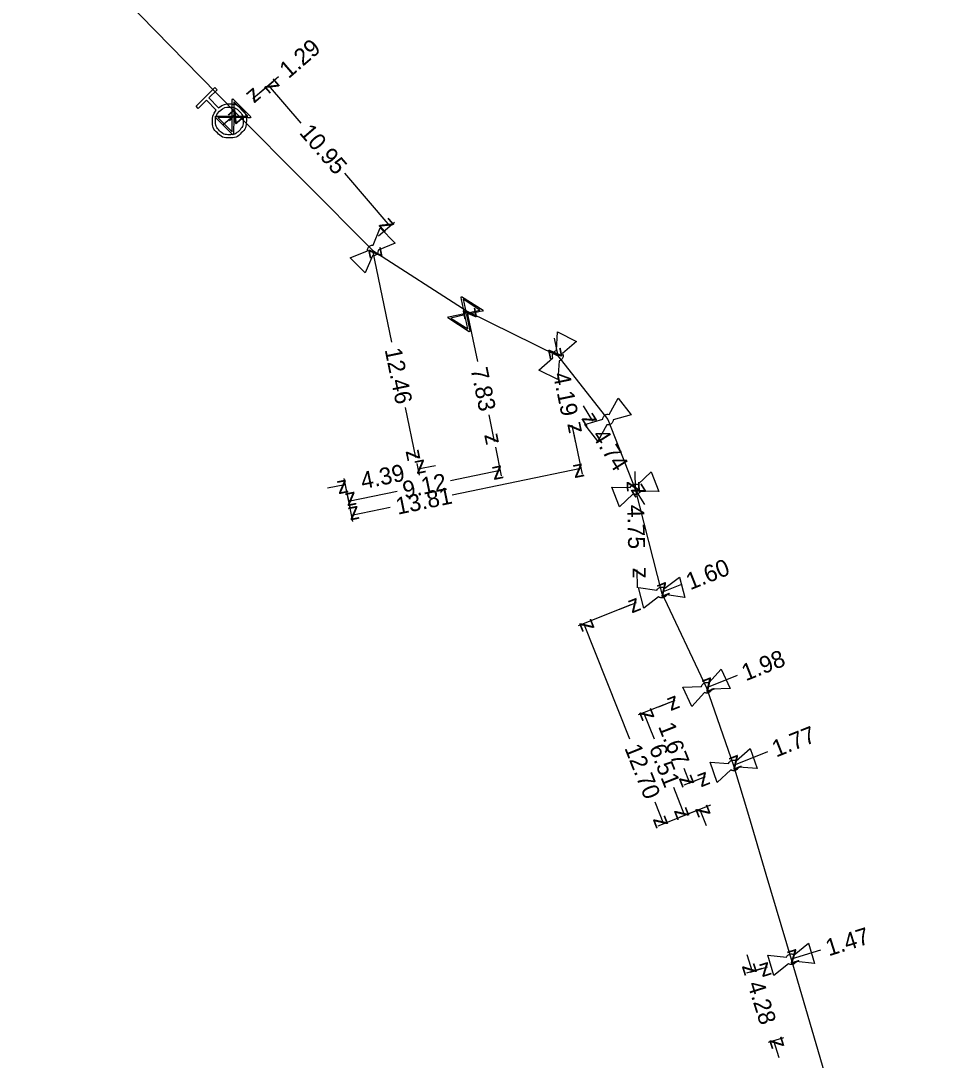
# Model space of a CAD drawing. Extents: x -638315 to -636370, y -1116147 to -1115110.
# Drawn here: x -637075 to -637021, y -1115890.1 to -1115828.9 of the extents above; entities that cross this region are included whole.
import ezdxf

# ---------------------------------------------------------------- set-up
doc = ezdxf.new("R2010")
doc.units = 0
for name, color, linetype in [('Default', 7, 'Continuous'), ('VP Hydrant', 7, 'Continuous'), ('VP Kótování', 7, 'Continuous'), ('VP Lomový bod', 7, 'Continuous'), ('VP Přípojka', 7, 'Continuous'), ('VP Řad', 7, 'Continuous'), ('VP Šoupě', 7, 'Continuous')]:
    doc.layers.add(name, color=color, linetype=linetype)

msp = doc.modelspace()

# ---------------------------------------------------------------- linework, layer by layer
at = {"layer": 'Default'}
for points in [[(-637063.308, -1115834.03), (-637063.032, -1115833.797), (-637062.666, -1115833.799), (-637062.253, -1115833.801), (-637061.96, -1115834.096), (-637061.668, -1115834.39), (-637061.669, -1115834.803), (-637061.671, -1115835.217), (-637061.966, -1115835.51), (-637062.258, -1115835.801), (-637062.671, -1115835.801), (-637063.085, -1115835.801), (-637063.377, -1115835.507), (-637063.671, -1115835.213), (-637063.671, -1115834.8), (-637063.673, -1115834.432), (-637063.438, -1115834.159)], [(-637063.246, -1115834.225), (-637063.485, -1115834.463), (-637063.486, -1115834.799), (-637063.487, -1115835.134), (-637063.248, -1115835.374), (-637063.01, -1115835.613), (-637062.674, -1115835.614), (-637062.339, -1115835.614), (-637062.099, -1115835.376), (-637061.861, -1115835.139), (-637061.86, -1115834.803), (-637061.858, -1115834.466), (-637062.097, -1115834.227), (-637062.335, -1115833.988), (-637062.671, -1115833.987), (-637063.006, -1115833.986), (-637063.246, -1115834.225)], [(-637054.532, -1115842.452), (-637054.536, -1115842.4), (-637054.521, -1115842.347), (-637054.499, -1115842.266), (-637054.441, -1115842.208), (-637054.383, -1115842.151), (-637054.299, -1115842.127), (-637054.248, -1115842.113), (-637054.195, -1115842.117)], [(-637053.907, -1115842.407), (-637053.904, -1115842.459), (-637053.917, -1115842.511), (-637053.942, -1115842.593), (-637054, -1115842.651), (-637054.058, -1115842.709), (-637054.139, -1115842.731), (-637054.192, -1115842.746), (-637054.244, -1115842.741)], [(-637043.607, -1115848.753), (-637043.628, -1115848.704), (-637043.632, -1115848.65), (-637043.637, -1115848.566), (-637043.6, -1115848.492), (-637043.564, -1115848.419), (-637043.493, -1115848.37), (-637043.449, -1115848.339), (-637043.398, -1115848.326)], [(-637043.031, -1115848.507), (-637043.011, -1115848.555), (-637043.007, -1115848.608), (-637043.003, -1115848.694), (-637043.039, -1115848.768), (-637043.076, -1115848.841), (-637043.145, -1115848.889), (-637043.19, -1115848.92), (-637043.241, -1115848.932)], [(-637040.672, -1115852.376), (-637040.67, -1115852.323), (-637040.649, -1115852.273), (-637040.617, -1115852.195), (-637040.553, -1115852.144), (-637040.489, -1115852.094), (-637040.403, -1115852.081), (-637040.35, -1115852.072), (-637040.299, -1115852.083)], [(-637040.046, -1115852.404), (-637040.048, -1115852.456), (-637040.068, -1115852.505), (-637040.102, -1115852.585), (-637040.166, -1115852.636), (-637040.231, -1115852.686), (-637040.314, -1115852.699), (-637040.368, -1115852.707), (-637040.42, -1115852.697)], [(-637039.045, -1115856.397), (-637039.028, -1115856.347), (-637038.993, -1115856.304), (-637038.94, -1115856.239), (-637038.864, -1115856.209), (-637038.788, -1115856.179), (-637038.702, -1115856.191), (-637038.649, -1115856.198), (-637038.603, -1115856.223)], [(-637038.454, -1115856.604), (-637038.471, -1115856.653), (-637038.505, -1115856.695), (-637038.56, -1115856.761), (-637038.636, -1115856.791), (-637038.712, -1115856.821), (-637038.796, -1115856.809), (-637038.85, -1115856.801), (-637038.896, -1115856.776)], [(-637037.48, -1115862.441), (-637037.457, -1115862.394), (-637037.417, -1115862.356), (-637037.356, -1115862.298), (-637037.277, -1115862.278), (-637037.198, -1115862.257), (-637037.114, -1115862.28), (-637037.063, -1115862.294), (-637037.02, -1115862.324)], [(-637036.919, -1115862.72), (-637036.942, -1115862.767), (-637036.98, -1115862.804), (-637037.044, -1115862.863), (-637037.123, -1115862.883), (-637037.202, -1115862.903), (-637037.283, -1115862.881), (-637037.336, -1115862.867), (-637037.379, -1115862.837)], [(-637034.851, -1115868.107), (-637034.837, -1115868.056), (-637034.806, -1115868.012), (-637034.757, -1115867.943), (-637034.683, -1115867.908), (-637034.609, -1115867.873), (-637034.523, -1115867.879), (-637034.47, -1115867.883), (-637034.422, -1115867.904)], [(-637034.247, -1115868.274), (-637034.261, -1115868.324), (-637034.292, -1115868.368), (-637034.342, -1115868.438), (-637034.416, -1115868.473), (-637034.49, -1115868.508), (-637034.574, -1115868.502), (-637034.629, -1115868.498), (-637034.677, -1115868.476)], [(-637033.25, -1115872.645), (-637033.231, -1115872.596), (-637033.195, -1115872.555), (-637033.14, -1115872.492), (-637033.062, -1115872.465), (-637032.985, -1115872.438), (-637032.9, -1115872.453), (-637032.847, -1115872.462), (-637032.802, -1115872.489)], [(-637032.667, -1115872.875), (-637032.687, -1115872.923), (-637032.722, -1115872.964), (-637032.78, -1115873.028), (-637032.857, -1115873.055), (-637032.934, -1115873.082), (-637033.017, -1115873.067), (-637033.071, -1115873.057), (-637033.116, -1115873.03)], [(-637029.845, -1115884.053), (-637029.824, -1115884.004), (-637029.786, -1115883.965), (-637029.728, -1115883.904), (-637029.649, -1115883.881), (-637029.571, -1115883.858), (-637029.486, -1115883.877), (-637029.435, -1115883.888), (-637029.39, -1115883.917)], [(-637029.274, -1115884.309), (-637029.295, -1115884.356), (-637029.332, -1115884.395), (-637029.393, -1115884.457), (-637029.471, -1115884.48), (-637029.55, -1115884.503), (-637029.632, -1115884.484), (-637029.685, -1115884.472), (-637029.729, -1115884.443)]]:
    msp.add_open_spline(points, degree=3, dxfattribs=at)
at = {"layer": 'VP Hydrant'}
msp.add_lwpolyline([(-637063.438, -1115834.159), (-637064.016, -1115833.578), (-637064.505, -1115834.065), (-637064.635, -1115833.934), (-637063.527, -1115832.832), (-637063.398, -1115832.962), (-637063.886, -1115833.448), (-637063.308, -1115834.03)], dxfattribs=at)
at = {"layer": 'VP Kótování'}
for points in [[(-637059.774, -1115832.193), (-637061.289, -1115833.501)], [(-637061.024, -1115833.272), (-637060.096, -1115832.472)], [(-637058.445, -1115834.923), (-637060.361, -1115832.701)], [(-637063.064, -1115835.033), (-637062.269, -1115834.347)], [(-637055.891, -1115837.884), (-637053.212, -1115840.99)], [(-637053.875, -1115841.561), (-637052.947, -1115840.761)], [(-637053.105, -1115847.828), (-637054.22, -1115842.43)], [(-637048.037, -1115848.978), (-637048.649, -1115846.013)], [(-637043.532, -1115847.602), (-637043.32, -1115848.63)], [(-637052.308, -1115851.688), (-637051.7, -1115854.634)], [(-637041.828, -1115851.59), (-637041.27, -1115852.48)], [(-637047.388, -1115852.121), (-637047.067, -1115853.677)], [(-637042.262, -1115853.757), (-637042.474, -1115852.729)], [(-637042.403, -1115853.072), (-637041.881, -1115855.6)], [(-637046.996, -1115854.02), (-637046.647, -1115855.711)], [(-637051.629, -1115854.977), (-637051.488, -1115855.661)], [(-637050.53, -1115855.106), (-637051.559, -1115855.319)], [(-637049.649, -1115855.973), (-637046.718, -1115855.368)], [(-637049.539, -1115856.824), (-637041.952, -1115855.258)], [(-637038.774, -1115855.45), (-637038.75, -1115856.5)], [(-637056.886, -1115856.418), (-637055.858, -1115856.206)], [(-637055.928, -1115855.864), (-637055.406, -1115858.392)], [(-637055.928, -1115855.864), (-637055.787, -1115856.548)], [(-637055.928, -1115855.864), (-637055.579, -1115857.555)], [(-637052.791, -1115856.622), (-637055.65, -1115857.212)], [(-637038.192, -1115857.39), (-637038.75, -1115856.5)], [(-637053.195, -1115857.579), (-637055.477, -1115858.05)], [(-637038.616, -1115862.3), (-637038.64, -1115861.25)], [(-637036.024, -1115862.112), (-637037.2, -1115862.58)], [(-637039.008, -1115863.299), (-637042.108, -1115864.532)], [(-637039.659, -1115863.558), (-637038.683, -1115863.17)], [(-637039.07, -1115871.223), (-637041.783, -1115864.403)], [(-637032.751, -1115867.475), (-637034.55, -1115868.19)], [(-637036.719, -1115869.052), (-637038.573, -1115869.789)], [(-637037.37, -1115869.311), (-637036.394, -1115868.923)], [(-637037.627, -1115871.221), (-637038.248, -1115869.66)], [(-637030.959, -1115871.965), (-637032.96, -1115872.76)], [(-637035.898, -1115872.933), (-637035.557, -1115873.792)], [(-637035.584, -1115873.803), (-637034.608, -1115873.415)], [(-637036.507, -1115874.04), (-637035.844, -1115875.707)], [(-637034.933, -1115873.544), (-637035.882, -1115873.921)], [(-637037.605, -1115874.907), (-637037.09, -1115876.203)], [(-637034.315, -1115875.099), (-637037.415, -1115876.332)], [(-637034.315, -1115875.099), (-637036.169, -1115875.836)], [(-637034.315, -1115875.099), (-637035.264, -1115875.476)], [(-637034.551, -1115876.323), (-637034.939, -1115875.347)], [(-637032.175, -1115883.901), (-637031.861, -1115884.902)], [(-637027.833, -1115883.638), (-637029.56, -1115884.18)], [(-637031.295, -1115884.725), (-637032.195, -1115885.007)], [(-637031.963, -1115884.935), (-637030.961, -1115884.62)], [(-637030.014, -1115888.805), (-637030.914, -1115889.087)], [(-637030.265, -1115889.984), (-637030.58, -1115888.982)]]:
    msp.add_lwpolyline(points, dxfattribs=at)
at = {"layer": 'VP Lomový bod'}
for points in [[(-637054.195, -1115842.117), (-637053.776, -1115841.105)], [(-637053.776, -1115841.105), (-637052.893, -1115841.991), (-637053.907, -1115842.407)], [(-637054.244, -1115842.741), (-637054.665, -1115843.755), (-637055.547, -1115842.869), (-637054.532, -1115842.452)], [(-637043.398, -1115848.326), (-637043.33, -1115847.232)], [(-637043.33, -1115847.232), (-637042.208, -1115847.783), (-637043.031, -1115848.507)], [(-637043.241, -1115848.932), (-637043.31, -1115850.028), (-637044.432, -1115849.477), (-637043.607, -1115848.753)], [(-637040.299, -1115852.083), (-637039.764, -1115851.126)], [(-637039.764, -1115851.126), (-637038.991, -1115852.108), (-637040.046, -1115852.404)], [(-637040.42, -1115852.697), (-637040.955, -1115853.654), (-637041.728, -1115852.672), (-637040.672, -1115852.376)], [(-637038.603, -1115856.223), (-637037.814, -1115855.462)], [(-637037.814, -1115855.462), (-637037.358, -1115856.626), (-637038.454, -1115856.604)], [(-637038.896, -1115856.776), (-637039.686, -1115857.538), (-637040.142, -1115856.374), (-637039.045, -1115856.397)], [(-637037.02, -1115862.324), (-637036.143, -1115861.666)], [(-637036.143, -1115861.666), (-637035.834, -1115862.877), (-637036.919, -1115862.72)], [(-637037.379, -1115862.837), (-637038.257, -1115863.495), (-637038.566, -1115862.284), (-637037.48, -1115862.441)], [(-637034.422, -1115867.904), (-637033.687, -1115867.091)], [(-637033.687, -1115867.091), (-637033.153, -1115868.222), (-637034.247, -1115868.274)], [(-637034.677, -1115868.476), (-637035.413, -1115869.289), (-637035.947, -1115868.159), (-637034.851, -1115868.107)], [(-637032.802, -1115872.489), (-637031.984, -1115871.759)], [(-637031.984, -1115871.759), (-637031.574, -1115872.939), (-637032.667, -1115872.875)], [(-637033.116, -1115873.03), (-637033.935, -1115873.761), (-637034.346, -1115872.58), (-637033.25, -1115872.645)], [(-637029.39, -1115883.917), (-637028.541, -1115883.225)], [(-637028.541, -1115883.225), (-637028.184, -1115884.423), (-637029.274, -1115884.309)], [(-637029.729, -1115884.443), (-637030.58, -1115885.136), (-637030.937, -1115883.938), (-637029.845, -1115884.053)]]:
    msp.add_lwpolyline(points, dxfattribs=at)
at = {"layer": 'VP Přípojka'}
for points in [[(-637062.269, -1115834.347), (-637062.47, -1115834.57), (-637062.67, -1115834.8)], [(-637048.76, -1115846.18), (-637048.649, -1115846.013)]]:
    msp.add_lwpolyline(points, dxfattribs=at)
at = {"layer": 'VP Řad'}
msp.add_lwpolyline([(-637074.96, -1115821.37), (-637064.392, -1115832.177), (-637062.269, -1115834.347), (-637054.22, -1115842.43), (-637048.649, -1115846.013), (-637043.32, -1115848.63), (-637040.36, -1115852.39), (-637038.75, -1115856.5), (-637037.2, -1115862.58), (-637034.55, -1115868.19), (-637032.96, -1115872.76), (-637032.085, -1115875.699), (-637031.05, -1115879.175), (-637029.56, -1115884.18), (-637027.5, -1115891.22), (-637025.68, -1115895.59), (-637023.88, -1115897.55), (-637021.76, -1115899.71), (-637021.41, -1115900.08), (-637021.02, -1115901.01)], dxfattribs=at)
at = {"layer": 'VP Šoupě'}
for points in [[(-637062.46, -1115833.503), (-637061.401, -1115834.566), (-637061.448, -1115834.612), (-637061.576, -1115834.608), (-637062.416, -1115834.607), (-637062.417, -1115835.577), (-637062.464, -1115835.624), (-637063.522, -1115834.561), (-637063.476, -1115834.515), (-637062.504, -1115834.519), (-637062.503, -1115833.679), (-637062.506, -1115833.549), (-637062.46, -1115833.503)], [(-637062.415, -1115833.68), (-637062.416, -1115834.519), (-637061.579, -1115834.52), (-637062.415, -1115833.68)], [(-637062.505, -1115835.45), (-637062.504, -1115834.607), (-637063.345, -1115834.606), (-637062.505, -1115835.45)], [(-637048.985, -1115845.143), (-637047.724, -1115845.954), (-637047.759, -1115846.01), (-637047.886, -1115846.033), (-637048.706, -1115846.212), (-637048.499, -1115847.161), (-637048.535, -1115847.216), (-637049.797, -1115846.405), (-637049.761, -1115846.349), (-637048.811, -1115846.145), (-637048.99, -1115845.324), (-637049.021, -1115845.198), (-637048.985, -1115845.143)], [(-637048.903, -1115845.307), (-637048.725, -1115846.126), (-637047.907, -1115845.948), (-637048.903, -1115845.307)], [(-637048.612, -1115847.055), (-637048.792, -1115846.231), (-637049.614, -1115846.411), (-637048.612, -1115847.055)]]:
    msp.add_lwpolyline(points, dxfattribs=at)

# ---------------------------------------------------------------- texts
at = {"layer": 'VP Kótování'}
for s, rotation, p in [('1.29', 40.8029, (-637059.182, -1115832.343)), ('z', 130.77676, (-637059.656, -1115832.753)), ('z', 220.80288, (-637061.237, -1115832.796)), ('z', 40.8029, (-637062.321, -1115835.052)), ('10.95', 310.77672, (-637058.595, -1115835.514)), ('z', 310.77674, (-637053.918, -1115840.938)), ('z', 101.66701, (-637053.629, -1115842.819)), ('z', 101.66317, (-637048.058, -1115846.402)), ('12.46', 281.66703, (-637053.524, -1115848.272)), ('z', 281.66166, (-637043.911, -1115848.241)), ('7.83', 281.66319, (-637048.456, -1115849.422)), ('4.19', 281.66164, (-637043.606, -1115849.716)), ('z', 302.08216, (-637041.959, -1115852.322)), ('z', 101.66162, (-637041.883, -1115853.118)), ('z', 281.66315, (-637047.658, -1115853.288)), ('4.74', 302.0822, (-637041.332, -1115853.323)), ('z', 281.66699, (-637052.291, -1115854.245)), ('4.39', 11.65809, (-637054.818, -1115856.501)), ('z', 191.65807, (-637051.17, -1115854.728)), ('z', 11.66473, (-637047.106, -1115855.959)), ('z', 11.66387, (-637042.341, -1115855.848)), ('9.12', 11.66473, (-637052.347, -1115857.041)), ('z', 11.65809, (-637056.246, -1115856.796)), ('z', 271.32659, (-637039.261, -1115856.012)), ('z', 122.08218, (-637038.061, -1115856.658)), ('z', 191.66477, (-637055.261, -1115856.622)), ('13.81', 11.66387, (-637052.751, -1115857.998)), ('z', 191.66385, (-637055.088, -1115857.459)), ('4.75', 271.32663, (-637039.229, -1115857.425)), ('1.60', 21.69476, (-637035.514, -1115862.447)), ('z', 91.32661, (-637038.129, -1115861.738)), ('z', 201.69474, (-637036.92, -1115861.931)), ('z', 21.69476, (-637038.963, -1115863.819)), ('z', 111.68832, (-637041.133, -1115864.683)), ('1.98', 21.67809, (-637032.241, -1115867.81)), ('z', 201.67807, (-637034.27, -1115867.541)), ('z', 21.67809, (-637036.674, -1115869.572)), ('z', 111.68042, (-637037.599, -1115869.94)), ('1.67', 291.67425, (-637037.419, -1115870.461)), ('1.77', 21.67539, (-637030.449, -1115872.3)), ('12.70', 291.68829, (-637039.406, -1115871.733)), ('6.51', 291.68044, (-637037.963, -1115871.731)), ('z', 201.67543, (-637032.68, -1115872.111)), ('z', 291.67427, (-637036.206, -1115873.512)), ('z', 21.67539, (-637034.888, -1115874.064)), ('z', 291.6804, (-637036.493, -1115875.427)), ('z', 111.67423, (-637034.29, -1115875.627)), ('z', 291.6883, (-637037.739, -1115875.923)), ('1.47', 17.43551, (-637027.349, -1115884.01)), ('z', 197.43549, (-637029.233, -1115883.553)), ('z', 287.43077, (-637032.488, -1115884.575)), ('z', 17.43551, (-637031.288, -1115885.247)), ('4.28', 287.43075, (-637032.155, -1115885.635)), ('z', 107.43073, (-637029.953, -1115889.31))]:
    msp.add_text(s, height=1, rotation=rotation, dxfattribs=at).set_placement(p)

doc.saveas('drawing.dxf')
